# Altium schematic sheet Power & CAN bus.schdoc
size 286 x 213 mm
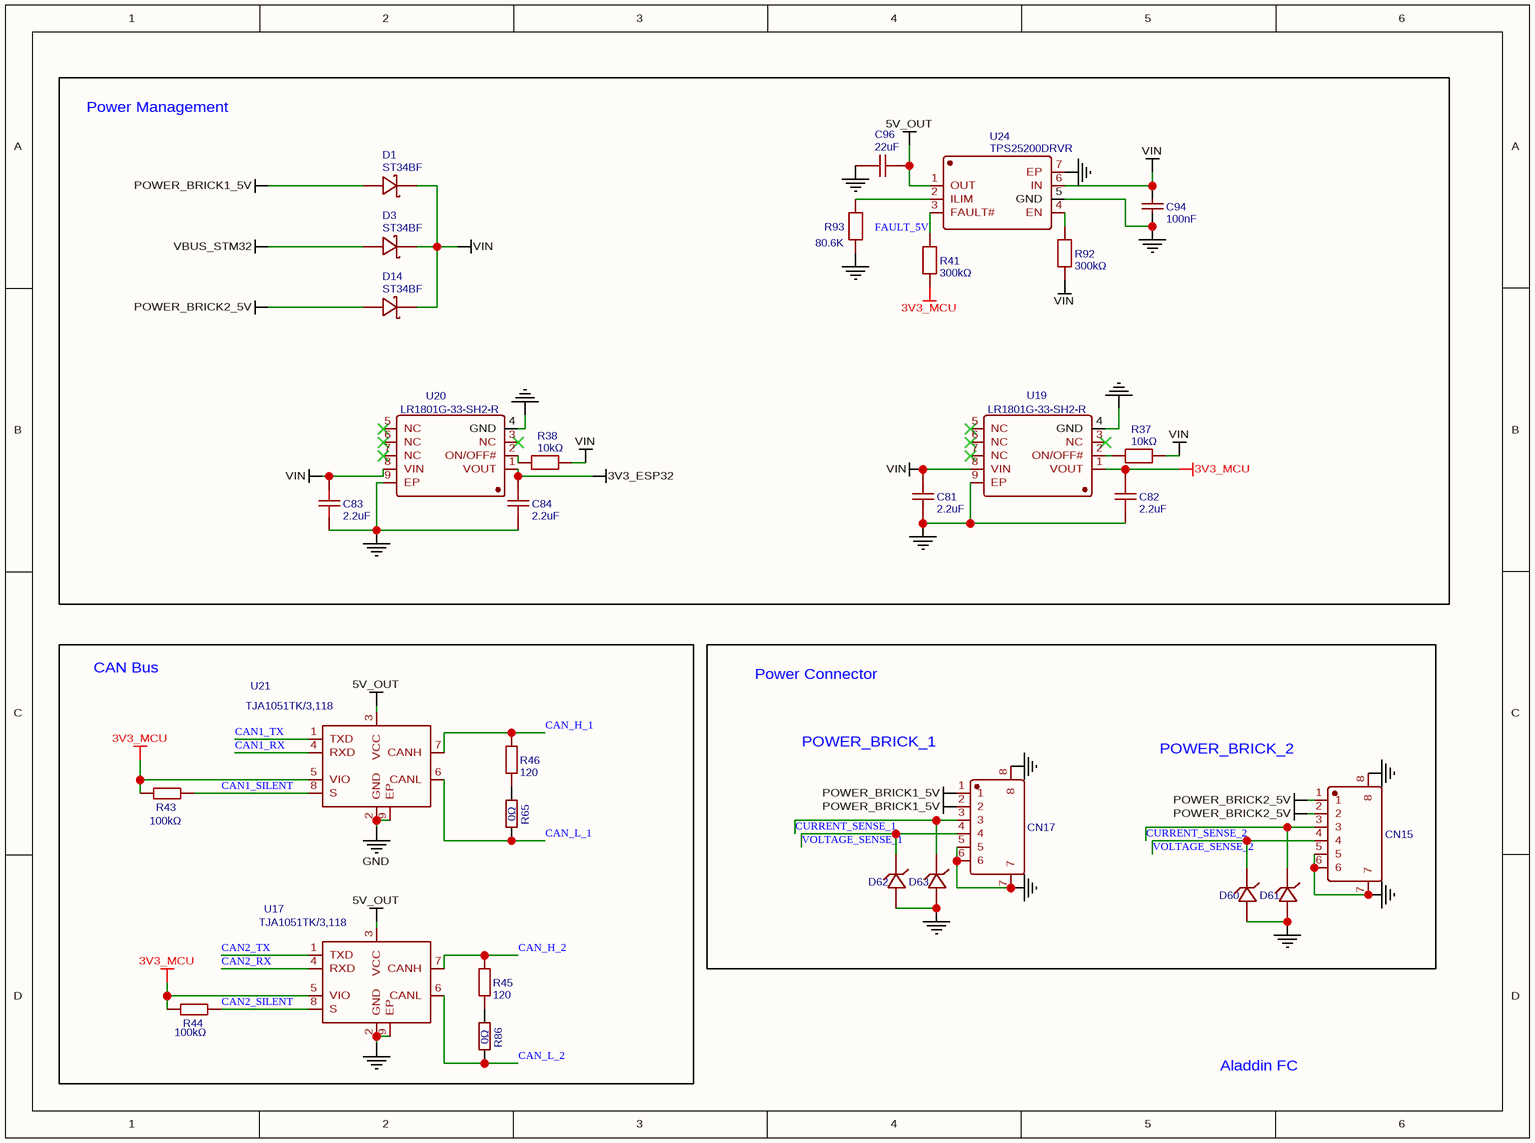
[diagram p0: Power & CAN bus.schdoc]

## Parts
C81  2.2uF  [C0805]
C82  2.2uF  [C0805]
C83  2.2uF  [C0805]
C84  2.2uF  [C0805]
C94  100nF  [C0805]
C96  22uF  [C0805]
CN15  A1257WV-S-6P  [CONN-SMD_A1257WV-S-6P]  (value not drawn)
CN17  A1257WV-S-6P  [CONN-SMD_A1257WV-S-6P]  (value not drawn)
D1  ST34BF  [SMBF_L4.3-W3.6-LS5.3-RD]
D3  ST34BF  [SMBF_L4.3-W3.6-LS5.3-RD]
D14  ST34BF  [SMBF_L4.3-W3.6-LS5.3-RD]
D60  ESD9X5V-2/TR  [FBP-02C_L1.0-W0.6-RD]  (value not drawn)
D61  ESD9X5V-2/TR  [FBP-02C_L1.0-W0.6-RD]  (value not drawn)
D62  ESD9X5V-2/TR  [FBP-02C_L1.0-W0.6-RD]  (value not drawn)
D63  ESD9X5V-2/TR  [FBP-02C_L1.0-W0.6-RD]  (value not drawn)
R37  10kΩ  [R0805]
R38  10kΩ  [R0805]
R41  300kΩ  [R0805]
R43  100kΩ  [R0805]
R44  100kΩ  [R0805]
R45  120  [R0805]
R46  120  [R0805]
R65  0Ω  [R0805]
R86  0Ω  [R0805]
R92  300kΩ  [R0805]
R93  RC0805DR-0780K6L  [R0805]  (value not drawn)
U17  TJA1051TK/3,118  [HVSON-8_L3.0-W3.0-P0.65-BL-EP]
U19  LR1801G-33-SH2-R  [HSOP-8_L5.0-W4.0-P1.27-LS6.2-BL-EP]
U20  LR1801G-33-SH2-R  [HSOP-8_L5.0-W4.0-P1.27-LS6.2-BL-EP]
U21  TJA1051TK/3,118  [HVSON-8_L3.0-W3.0-P0.65-BL-EP]
U24  TPS25200DRVR  [WSON-6_L2.0-W2.0-P0.65-TL-EP]

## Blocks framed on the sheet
Power Management: C81-C84 C94 C96 D1 D3 D14 R37 R38 R41 R92 R93 U19 U20 U24
CAN Bus: R43-R46 R65 R86 U17 U21

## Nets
3V3_ESP32: C84.2 U20.1(VOUT)
3V3_MCU: C82.2 R41.1 R43.2 R44.1 U17.5(VIO) U19.1(VOUT) U21.5(VIO)
5V_OUT: C96.2 U17.3(VCC) U21.3(VCC) U24.1(OUT)
GND: C81.2 C82.1 C83.1 C84.1 C94.1 C96.1 CN15.5 CN15.6 CN15.7 CN15.8 CN17.5 CN17.6 CN17.7 CN17.8 D60.2 D61.2 D62.2 D63.2 R93.1 U17.2(GND) U17.9(EP) U19.4(GND) U19.9(EP) U20.4(GND) U20.9(EP) U21.2(GND) U21.9(EP) U24.5(GND) U24.7(EP)
POWER_BRICK1_5V: CN17.1 CN17.2 D1.2(A)
POWER_BRICK2_5V: CN15.1 CN15.2 D14.2(A)
VBUS_STM32: D3.2(A)
VIN: C81.1 C83.2 C94.2 D1.1(C) D3.1(C) D14.1(C) R37.2 R38.2 R92.1 U19.8(VIN) U20.8(VIN) U24.6(IN)
CAN1_RX: U21.4(RXD)
CAN1_SILENT: R43.1 U21.8(S)
CAN1_TX: U21.1(TXD)
CAN2_RX: U17.4(RXD)
CAN2_SILENT: R44.2 U17.8(S)
CAN2_TX: U17.1(TXD)
CAN_H_1: R46.2 U21.7(CANH)
CAN_H_2: R45.1 U17.7(CANH)
CAN_L_1: R65.1 U21.6(CANL)
CAN_L_2: R86.1 U17.6(CANL)
CURRENT_SENSE_1: CN17.3 D63.1
CURRENT_SENSE_2: CN15.3 D61.1
FAULT_5V: R41.2 U24.3(FAULT#)
VOLTAGE_SENSE_1: CN17.4 D62.1
VOLTAGE_SENSE_2: CN15.4 D60.1
NetR37_1: R37.1 U19.2(ON/OFF#)
NetR38_1: R38.1 U20.2(ON/OFF#)
NetR45_2: R45.2 R86.2
NetR46_1: R46.1 R65.2
NetR92_2: R92.2 U24.4(EN)
NetR93_2: R93.2 U24.2(ILIM)

Not connected (* = marked no-connect by the designer): U19 3(NC)* 5(NC)* 6(NC)* 7(NC)*; U20 3(NC)* 5(NC)* 6(NC)* 7(NC)*

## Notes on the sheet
- (near R93) 80.6K
- Power Connector
- POWER_BRICK_1
- POWER_BRICK_2
- Aladdin FC

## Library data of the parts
C81-C84 = 2.2uF: BOM_Manufacturer: YAGEO; BOM_Manufacturer Part: CC0805ZRY5V7BB225; nameAlias: Capacitance; Contributor: LCSC
C94 = 100nF: BOM_Manufacturer Part: CL21B104KBCNNNC; BOM_Manufacturer: SAMSUNG; nameAlias: Capacitance
C96 = 22uF: BOM_Manufacturer: SAMSUNG(三星); BOM_Manufacturer Part: CL21A226MAQNNNE; nameAlias: Capacitance
CN15 CN17 = A1257WV-S-6P: BOM_Manufacturer: CJT(长江连接器); Contributor: LCSC
D1 D3 D14 = ST34BF: BOM_Manufacturer: MDD（Microdiode Electronics）; Contributor: LCSC
D60-D63 = ESD9X5V-2/TR: BOM_Manufacturer: Will Semicon; Contributor: LCSC
R37 R38 = 10kΩ: BOM_Manufacturer: Viking Tech; BOM_Manufacturer Part: ARG05BTC1002; Resistance (Ohms): 10K; nameAlias: Resistance; Contributor: LCSC
R41 R92 = 300kΩ: BOM_Manufacturer: PANASONIC; BOM_Manufacturer Part: ERJ6GEYJ304V; Resistance (Ohms): 300K; nameAlias: Resistance; Contributor: LCSC
R43 R44 = 100kΩ: BOM_Manufacturer: Viking Tech; BOM_Manufacturer Part: ARG05BTC1003; Resistance (Ohms): 100K; nameAlias: Resistance; Contributor: LCSC
R45 R46 = 120: BOM_Manufacturer: YAGEO; BOM_Manufacturer Part: AC0805FR-07120RL; nameAlias: Resistance (Ohms); Contributor: LCSC; Resistance: 120Ω
R65 R86 = 0Ω: BOM_Manufacturer: UniOhm; BOM_Manufacturer Part: 0805W8F0000T5E; nameAlias: Resistance; Resistance (Ohms): 0
R93 = RC0805DR-0780K6L: BOM_Manufacturer: YAGEO(国巨); Resistance: 80.6kΩ; Contributor: lcsc
U17 U21 = TJA1051TK/3,118: BOM_Manufacturer: NXP
U19 U20 = LR1801G-33-SH2-R: BOM_Manufacturer: Unisonic Tech; Contributor: LCSC
U24 = TPS25200DRVR: BOM_Manufacturer: TI; Contributor: LCSC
